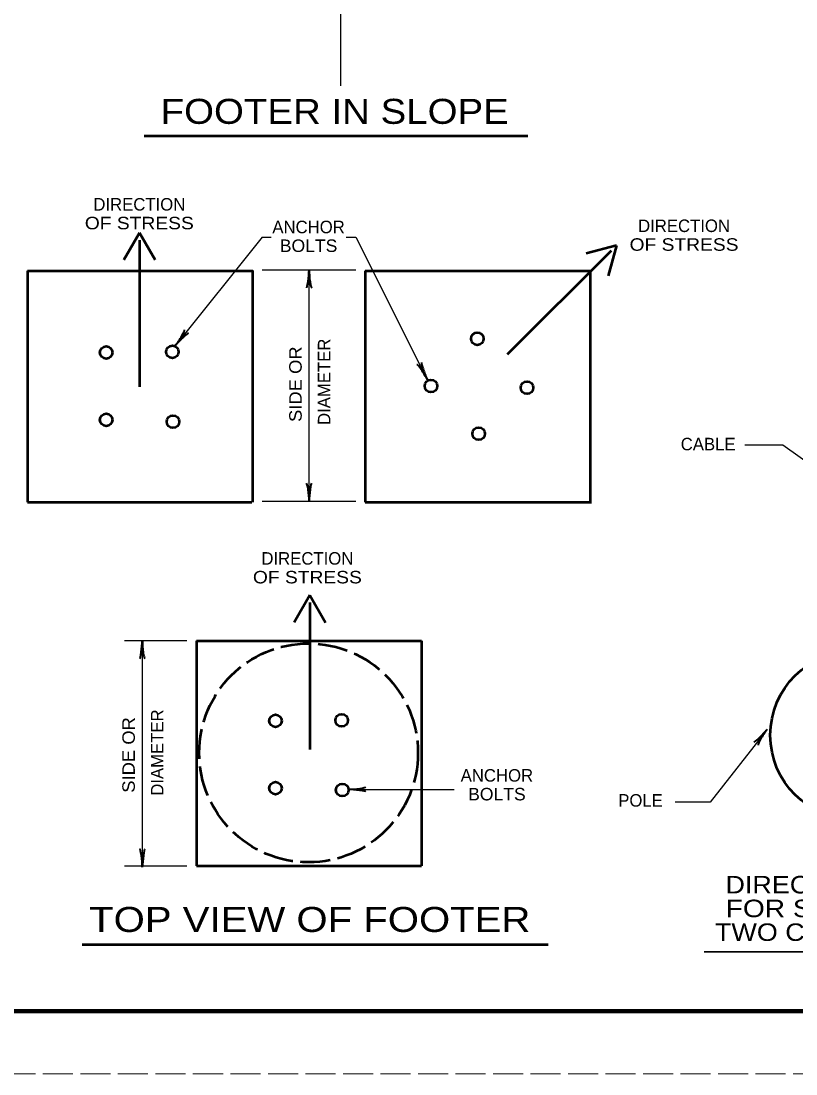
# Model space of a CAD drawing. Extents: x -560 to 120, y 26 to 466.
# Drawn here: x -392.1 to -268.1, y 25.8 to 194.2 of the extents above; entities that cross this region are included whole.
import ezdxf
from ezdxf.enums import TextEntityAlignment as Align

# ---------------------------------------------------------------- set-up
doc = ezdxf.new("R2010")
doc.units = 0
doc.header["$LTSCALE"] = 0.8
doc.linetypes.add('LONG_DASHED', pattern=[7.5, 6, -1.5])
doc.layers.add('1', color=7, linetype='Continuous', lineweight=53)
doc.layers.add('61', color=7, linetype='Continuous', lineweight=35)

msp = doc.modelspace()

# ---------------------------------------------------------------- linework, layer by layer
at = {"layer": '1', "lineweight": 25}
for p, q in [((-340.9302, 183.8417), (-340.9302, 205.331)), ((-353.5034, 159.6527), (-367.425, 142.2985)), ((-353.5034, 159.6527), (-352.0732, 159.6527)), ((-340.0587, 159.6527), (-338.5034, 159.6527)), ((-338.5034, 159.6527), (-327.0908, 136.8634)), ((-353.5034, 154.4083), (-338.5034, 154.4083)), ((-346.0034, 117.4083), (-346.0034, 154.4083)), ((-270.2215, 126.3662), (-276.2765, 126.3662)), ((-259.5827, 118.8222), (-270.2215, 126.3662)), ((-375.5544, 95.114), (-365.5544, 95.114)), ((-372.6938, 95.1141), (-372.6938, 58.8798)), ((-346.0166, 95.0884), (-346.0166, 83.0739)), ((-272.7362, 80.9092), (-281.8276, 69.3032)), ((-339.7968, 71.3234), (-322.7968, 71.3234)), ((-281.8276, 69.3032), (-287.4471, 69.3032)), ((-375.5544, 59.114), (-365.5544, 59.114))]:
    msp.add_line(p, q, dxfattribs=at)
at = {"layer": '1'}
for p, q in [((-372.3837, 175.8631), (-311.0065, 175.8631)), ((-373.1461, 160.3432), (-375.6461, 156.013)), ((-373.1461, 160.3432), (-370.6461, 156.013)), ((-373.1461, 159.199), (-373.1461, 135.699)), ((-314.2607, 140.9158), (-297.6437, 157.5327)), ((-296.8415, 158.3166), (-301.6712, 157.0224)), ((-296.8415, 158.3166), (-298.1357, 153.4868)), ((-337.0482, 154.2752), (-337.0482, 117.2752)), ((-337.0482, 154.2752), (-301.0482, 154.2752)), ((-301.0482, 154.2752), (-301.0482, 117.2752)), ((-337.0482, 117.2752), (-300.8444, 117.2752)), ((-345.8751, 102.3683), (-348.3751, 98.0382)), ((-345.8751, 102.3683), (-343.3751, 98.0382)), ((-345.8751, 101.2242), (-345.8751, 77.7242)), ((-364.0166, 95.0884), (-328.0166, 95.0884)), ((-364.0166, 95.0884), (-364.0166, 59.0884)), ((-328.0166, 95.0884), (-328.0166, 59.0884)), ((-364.0166, 59.0884), (-328.0166, 59.0884)), ((-382.3246, 46.5082), (-307.7578, 46.5082))]:
    msp.add_line(p, q, dxfattribs=at)
at = {"layer": '1', "lineweight": 35}
msp.add_line((-282.7947, 45.3173), (-227.0857, 45.3173), dxfattribs=at)
at = {"layer": '1'}
for points in [[(-391.0482, 154.2752), (-391.0482, 135.7752), (-391.0482, 117.2752)], [(-391.0482, 154.2752), (-373.1179, 154.2752), (-355.0482, 154.2752), (-355.0482, 135.7752), (-355.0482, 117.2752)], [(-391.0482, 117.2752), (-373.1179, 117.2752), (-355.1876, 117.2752)]]:
    msp.add_lwpolyline(points, dxfattribs=at)
at = {"layer": '1', "lineweight": 25}
msp.add_lwpolyline([(-353.5034, 117.4083), (-345.9706, 117.4083), (-338.5034, 117.4083)], dxfattribs=at)
at = {"layer": '1'}
for centre, radius in [((-319.0906, 143.4061), 1), ((-378.4618, 141.2119), 1), ((-367.8777, 141.3072), 1), ((-326.5073, 135.8546), 1), ((-311.1345, 135.5849), 1), ((-378.4618, 130.4371), 1), ((-367.7823, 130.151), 1), ((-318.8884, 128.2356), 1), ((-258.7122, 79.9902), 13.5), ((-351.3816, 82.2837), 1), ((-340.7974, 82.379), 1), ((-351.3816, 71.5088), 1), ((-340.7021, 71.2227), 1)]:
    msp.add_circle(centre, radius, dxfattribs=at)
at = {"layer": '1', "linetype": 'LONG_DASHED'}
msp.add_circle((-346.0902, 77.1633), 17.5, dxfattribs=at)
at = {"layer": '1', "lineweight": 40}
for centre, major_axis, ratio, start_param, end_param in [((-346.215, 153.2878), (-0.1757, -1.7565), 0.07063, 6.28230741, 8.55970261), ((-345.7271, 153.3171), (-0.1562, 1.7857), 0.122415, 0.89635335, 3.14159265), ((-366.9577, 143.3226), (-0.9956, -1.4906), 0.122415, 0.89635335, 3.14159265), ((-366.5588, 143.0401), (-1.2361, -1.2602), 0.07063, 3.14071475, 5.41810995), ((-327.8264, 137.7154), (0.9392, -1.5268), 0.122415, 0.89635335, 3.14159265), ((-327.4033, 137.9601), (-0.6294, 1.6492), 0.07063, 6.28230741, 8.55970261), ((-346.2797, 118.4995), (0.1562, -1.7857), 0.122415, 0.89635335, 3.14159265), ((-345.7918, 118.5288), (0.1757, 1.7565), 0.07063, 6.28230741, 8.55970261), ((-372.9054, 93.9936), (-0.1757, -1.7565), 0.07063, 6.28230741, 8.55970261), ((-372.4175, 94.0229), (-0.1562, 1.7857), 0.122415, 0.89635335, 3.14159265), ((-273.5937, 80.1576), (-1.2214, -1.2744), 0.07063, 6.28230741, 8.55970261), ((-273.1916, 79.8798), (0.9783, 1.502), 0.122415, 0.89635335, 3.14159265), ((-338.6763, 71.1118), (1.7565, -0.1757), 0.07063, 6.28230741, 8.55970261), ((-338.7056, 71.5997), (-1.7857, -0.1562), 0.122415, 0.89635335, 3.14159265), ((-372.9701, 59.9709), (0.1562, -1.7857), 0.122415, 0.89635335, 3.14159265), ((-372.4822, 60.0003), (0.1757, 1.7565), 0.07063, 6.28230741, 8.55970261)]:
    msp.add_ellipse(centre, major_axis=major_axis, ratio=ratio, start_param=start_param, end_param=end_param, dxfattribs=at)
at = {"layer": '61', "lineweight": 158}
msp.add_line((109.2791, 35.8027), (-529.7809, 35.8227), dxfattribs=at)
at = {"layer": '61', "linetype": 'LONG_DASHED', "lineweight": 13}
msp.add_line((120.2191, 25.8227), (-559.8409, 25.8027), dxfattribs=at)

# ---------------------------------------------------------------- texts
at = {"layer": '1'}
for s, height, width, p in [('FOOTER IN SLOPE', 4, 1.15, (-341.9094, 177.7832)), ('OF STRESS', 2, 1.15, (-373.1706, 160.9117)), ('BOLTS', 2, 1.05, (-346.0901, 157.2883)), ('OF STRESS', 2, 1.15, (-286.0174, 157.4789)), ('OF STRESS', 2, 1.15, (-346.2809, 104.2717)), ('BOLTS', 2, 1.05, (-315.9583, 69.563)), ('DIRECTION OF STRESS', 2.8, 1.15, (-254.7468, 54.681)), ('TOP VIEW OF FOOTER', 4, 1.2, (-345.8995, 48.5131)), ('FOR SIGNAL POLES w/', 2.8, 1.2, (-254.7468, 50.881)), ('TWO CABLES ATTACHED', 2.8, 1.15, (-254.7468, 47.081))]:
    msp.add_text(s, height=height, dxfattribs=dict(at, width=width)).set_placement(p, align=Align.CENTER)
for s, p in [('DIRECTION', (-373.1706, 163.9117)), ('ANCHOR', (-346.0901, 160.2883)), ('DIRECTION', (-286.0174, 160.4789)), ('DIRECTION', (-346.2809, 107.2717)), ('ANCHOR', (-315.9584, 72.563))]:
    msp.add_text(s, height=2, dxfattribs=at).set_placement(p, align=Align.CENTER)
for p in [(-342.611, 136.522), (-369.31, 77.2121)]:
    msp.add_text('DIAMETER', height=2, rotation=90, dxfattribs=at).set_placement(p, align=Align.CENTER)
at = {"layer": '1', "width": 1.1}
for p in [(-347.1879, 136.1406), (-373.8869, 76.8307)]:
    msp.add_text('SIDE OR', height=2, rotation=90, dxfattribs=at).set_placement(p, align=Align.CENTER)
at = {"layer": '1'}
for s, p in [('CABLE', (-277.7757, 125.5595)), ('POLE', (-289.4098, 68.563))]:
    msp.add_text(s, height=2, dxfattribs=at).set_placement(p, align=Align.RIGHT)

doc.saveas('drawing.dxf')
